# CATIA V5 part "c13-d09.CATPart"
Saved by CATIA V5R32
Part number: Part1
Bounding box of the stored display mesh (mm): x -14.877 to 14.877, y 0 to 225, z -14.877 to 14.877
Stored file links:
  D:\PROJECTS\Project 2022\CATIA V5 6R 2022\Resources\Part Files\c13_catia_v5_6r2022_prt\c13_catia_v5-6r2022_figr_13-37 & 38\c13-d09.CATPart
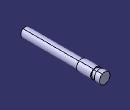
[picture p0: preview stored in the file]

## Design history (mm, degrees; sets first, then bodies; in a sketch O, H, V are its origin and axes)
Body1 (main body)
  Sketch1 on yz-plane, origin (0, 0, 0), H (0, 1, 0), V (0, 0, 1)
    axis line L1 (0, 0) -> (204.8018, 0)
    line L2 (0, 0) -> (0, 12.5)
    line L3 (160, 15) -> (200, 15)
    line L4 (200, 15) -> (200, 12.5)
    line L5 (200, 12.5) -> (210, 12.5)
    line L6 (210, 12.5) -> (210, 15)
    point P5 (210, 15)
    point P6 (210, 15)
    line L7 (210, 15) -> (225, 15)
    line L8 (225, 15) -> (225, 0)
    point P8 (225, 0)
    line L9 (225, 0) -> (0, 0)
    line L10 (160, 15) -> (160, 12.5)
    line L11 (160, 12.5) -> (0, 12.5)
    radius about axis L1 L7 = 15
    radius about axis L5 L1 = 12.5
    length L9 = 225
    length L5 = 10
    distance L4 L2 = 200
    radius about axis L11 L1 = 12.5
    length L11 = 160
    horizontal: L1 H, L3 H, L5 H, L7 H, L9 H, L11 H
    vertical: L2 V, L4 V, L6 V, L8 V, L10 V
    coincidence: P5 L3, P6 L3, P8 L1, P6 P5
  Shaft1: profile Sketch1, axis Sketch1.L1, angle 360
